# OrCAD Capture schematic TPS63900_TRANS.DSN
size D; title: TPS63900: 400-mA Buck-Boost Converter with Nanoampere; rev: 1.0; note: Datasheet: NA     EVM: NA; note: Synchronous Step Down Converter
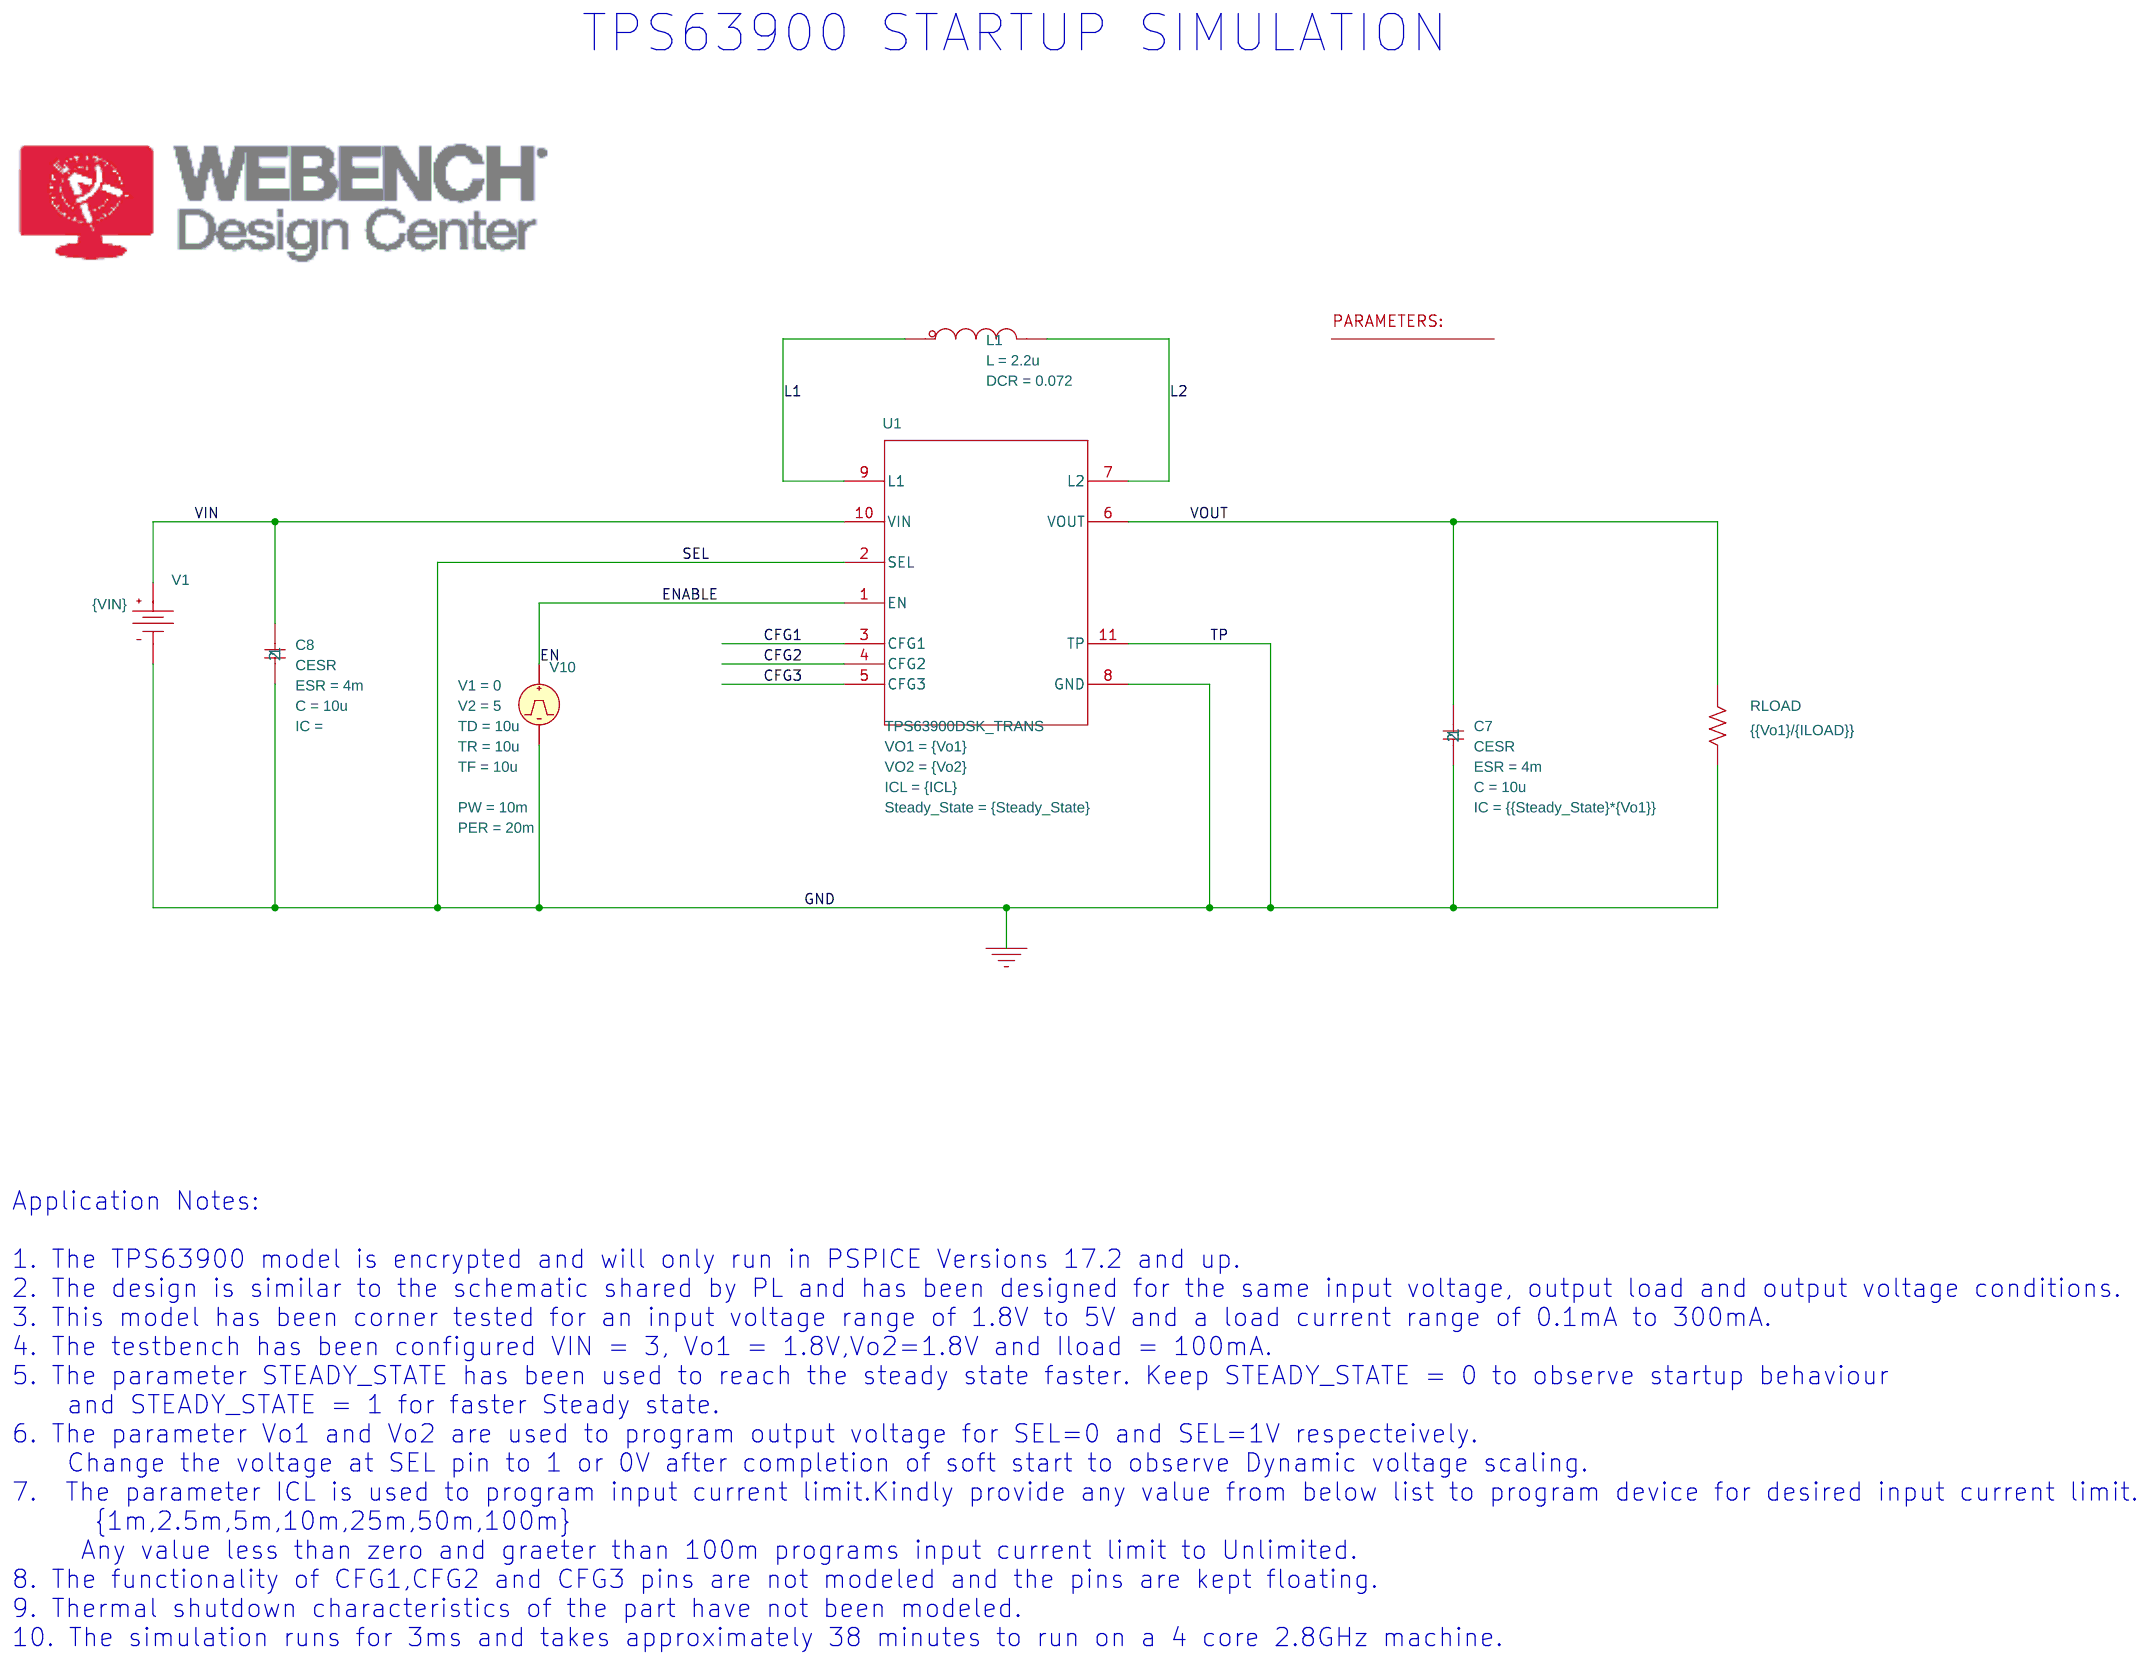
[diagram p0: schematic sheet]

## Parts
1  PARAM
C7  CESR
C8  CESR
L1  LDCR
RLOAD  {{Vo1}/{ILOAD}}  [AX/RC05]
U1  TPS63900DSK_TRANS  [DSK0010A]
V1  VDC
V10  VPULSE

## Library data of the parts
1 = PARAM: ICL: 0; ILOAD: 100m; Steady_State: 0; VIN: 3; Vo1: 1.8; Vo2: 1.8
C7 = CESR_1: C: 10u; ESR: 4m; IC: {{Steady_State}*{Vo1}}; PSpiceTemplate: X^@REFDES %1 %2 @MODEL PARAMS: ?C|C=@C||C=10U| ?ESR|ESR=@ESR||ESR=2M| ?IC|IC=@IC||IC=1N| ?X|X=@X||X=1|; X: 1
C8 = CESR: C: 10u; ESR: 4m; PSpiceTemplate: X^@REFDES %1 %2 @MODEL PARAMS: ?C|C=@C||C=10U| ?ESR|ESR=@ESR||ESR=2M| ?IC|IC=@IC||IC=1N| ?X|X=@X||X=1|; X: 1
L1 = LDCR_0: DCR: 0.072; L: 2.2u; PSpiceTemplate: X^@REFDES %IN %OUT @MODEL PARAMS:  ?L|L=@L||L=1u|  ?DCR|DCR=@DCR||DCR=0.01| ?IC|IC=@IC||IC=0|
RLOAD = R
U1 = TPS63900DSK_TRANS: ICL: {ICL}; Steady_State: {Steady_State}; VO1: {Vo1}; VO2: {Vo2}
V1 = VDC: DC: {VIN}
V10 = VPULSE: PER: 20m; PW: 10m; TD: 10u; TF: 10u; TR: 10u; V1: 0; V2: 5

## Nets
VIN: C8.1 U1.10(VIN) V1.0(+)
0: C7.2 C8.2 RLOAD.2 U1.2(SEL) U1.8(GND) U1.11(TP) V1.1(-) V10.2(-)
CFG1: U1.3(CFG1)
CFG2: U1.4(CFG2)
CFG3: U1.5(CFG3)
EN: U1.1(EN) V10.1(+)
L1: L1.1(IN) U1.9(L1)
L2: L1.3(OUT) U1.7(L2)
VOUT: C7.1 RLOAD.1 U1.6(VOUT)

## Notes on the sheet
- TPS63900 STARTUP SIMULATION
- Application Notes:
  1. The TPS63900 model is encrypted and will only run in PSPICE Versions 17.2 and up.
  2. The design is similar to the schematic shared by PL and has been designed for the same input voltage, output load and output voltage conditions.
  3. This model has been corner tested for an input voltage range of 1.8V to 5V and a load current range of 0.1mA to 300mA.
  4. The testbench has been configured VIN = 3, Vo1 = 1.8V,Vo2=1.8V and Iload = 100mA.
  5. The parameter STEADY_STATE has been used to reach the steady state faster. Keep STEADY_STATE = 0 to observe startup behaviour
      and STEADY_STATE = 1 for faster Steady state.
  6. The parameter Vo1 and Vo2 are used to program output voltage for SEL=0 and SEL=1V respecteively.
      Change the voltage at SEL pin to 1 or 0V after completion of soft start to observe Dynamic voltage scaling.
  7.  The parameter ICL is used to program input current limit.Kindly provide any value from below list to program device for desired input current limit.
        {1m,2.5m,5m,10m,25m,50m,100m}
       Any value less than zero and graeter than 100m programs input current limit to Unlimited.
  8. The functionality of CFG1,CFG2 and CFG3 pins are not modeled and the pins are kept floating.
  9. Thermal shutdown characteristics of the part have not been modeled.
  10. The simulation runs for 3ms and takes approximately 38 minutes to run on a 4 core 2.8GHz machine.
